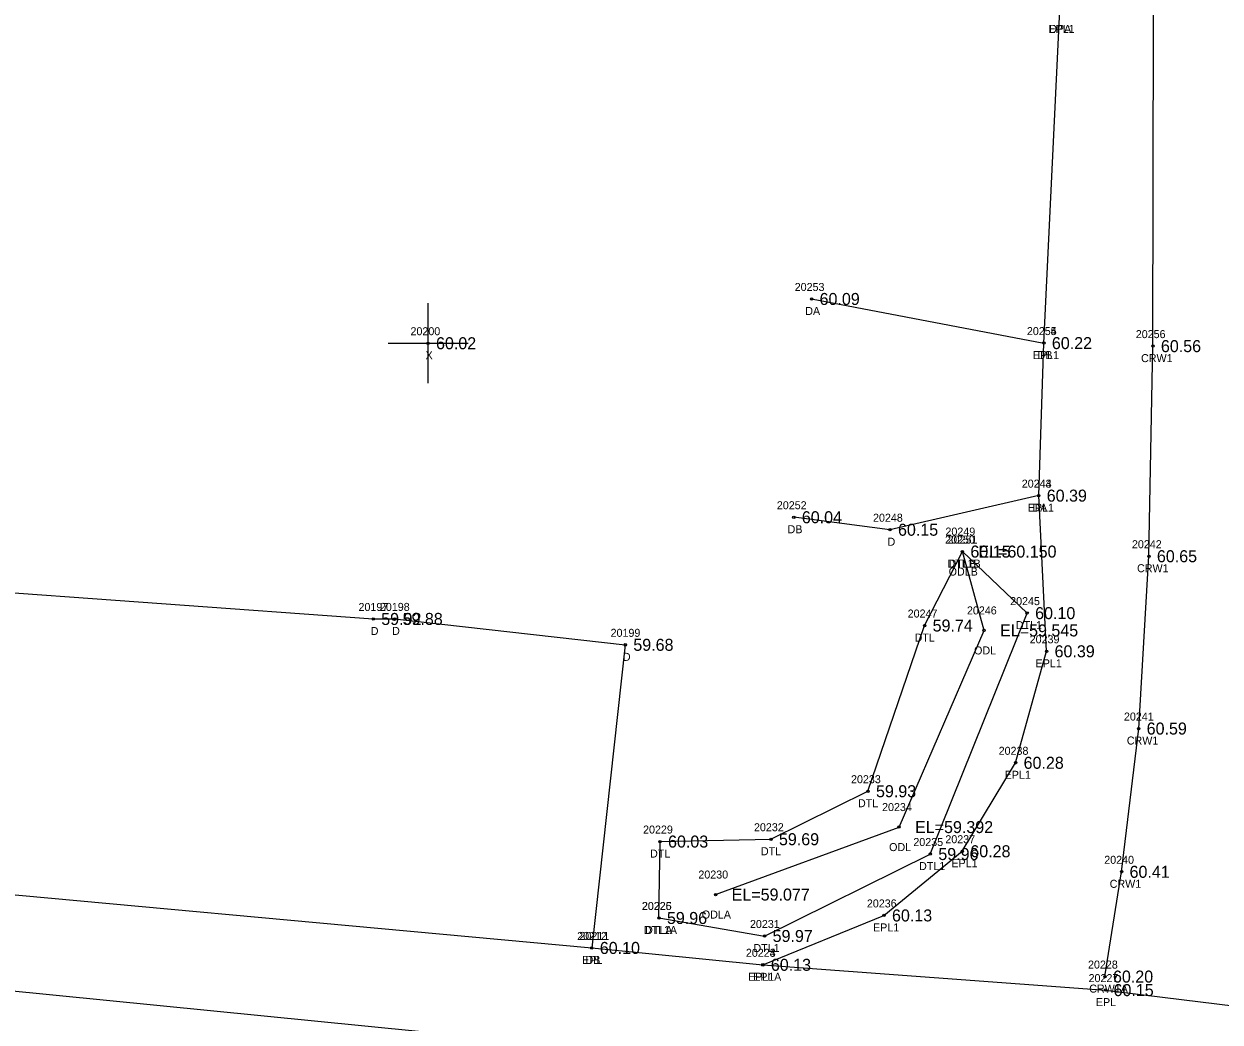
# Model space of a CAD drawing. Extents: x 2420351 to 2422725, y 845330 to 846558.
# Drawn here: x 2420818.7 to 2420968.2, y 845709.7 to 845834.4 of the extents above; entities that cross this region are included whole.
import ezdxf

# ---------------------------------------------------------------- set-up
doc = ezdxf.new("R2010")
doc.units = 0
for name, color, linetype in [('RD_DTM_BkLn1', 7, 'Continuous'), ('RD_EX_Driveway', 7, 'Continuous'), ('RD_EX_Driveway_txCode', 7, 'Continuous'), ('RD_EX_H2O', 7, 'Continuous'), ('RD_EX_H2O_txCode', 7, 'Continuous'), ('RD_EX_Misc', 7, 'Continuous'), ('RD_EX_Misc_txCode', 7, 'Continuous'), ('RD_EX_Road', 7, 'Continuous'), ('RD_EX_Road_txCode', 7, 'Continuous'), ('RD_EX_TX_Driveway_ELEV', 7, 'Continuous'), ('RD_EX_TX_H2O_ELEV', 7, 'Continuous'), ('RD_EX_TX_Misc_ELEV', 7, 'Continuous'), ('RD_EX_TX_Road_ELEV', 7, 'Continuous'), ('RD_HC_Survey_ELEV', 7, 'Continuous'), ('RD_HC_Survey_txCode', 7, 'Continuous'), ('RD_SMD_Locator', 7, 'Continuous')]:
    doc.layers.add(name, color=color, linetype=linetype)

msp = doc.modelspace()

# ---------------------------------------------------------------- linework, layer by layer
at = {"layer": 'RD_DTM_BkLn1'}
for points in [[(2420953.84, 845715.4), (2420955.91, 845728.49), (2420958.05, 845746.39), (2420959.33, 845767.92), (2420959.83, 845794.17), (2420960.04, 845896.62), (2420959.9, 845997.98), (2420960.79, 846105.06), (2420961.13, 846198.92)], [(2420378.71, 845690.53), (2420439.5, 845704.09), (2420489.95, 845712.49), (2420551.89, 845719.42), (2420551.95, 845719.57), (2420607.12, 845722.67), (2420682.92, 845723.04), (2420749.65, 845719.68), (2420796.31, 845715.7), (2420900.74, 845705.33), (2421018.16, 845694.11), (2421114.61, 845684.8), (2421175.74, 845680.1), (2421234.97, 845678.35), (2421292.42, 845679.46), (2421350.56, 845683.65), (2421414.53, 845692.12), (2421472.54, 845703.63), (2421533.08, 845718.31), (2421555.4, 845725.02), (2421609.81, 845741.71), (2421666.58, 845762.88), (2421744.67, 845798.22)]]:
    msp.add_lwpolyline(points, dxfattribs=at)
at = {"layer": 'RD_EX_Driveway'}
msp.add_line((2420917.17, 845800.06), (2420946.2, 845794.55), dxfattribs=at)
for points in [[(2420945.56, 845775.49), (2420926.97, 845771.23), (2420914.95, 845772.79)], [(2420809.42, 845763.93), (2420862.38, 845760.08), (2420865.05, 845760.09), (2420893.89, 845756.85), (2420889.7, 845718.98)]]:
    msp.add_lwpolyline(points, dxfattribs=at)
at = {"layer": 'RD_EX_H2O'}
for points in [[(2420898.09, 845722.72), (2420898.23, 845732.27), (2420912.09, 845732.56), (2420924.22, 845738.56), (2420931.3, 845759.26), (2420936.02, 845768.5)], [(2420898.09, 845722.72), (2420911.3, 845720.47), (2420932.01, 845730.71), (2420944.11, 845760.81), (2420936.02, 845768.5)], [(2420905.18, 845725.65), (2420928.1, 845734.08), (2420938.73, 845758.65), (2420936.02, 845768.5)]]:
    msp.add_lwpolyline(points, dxfattribs=at)
at = {"layer": 'RD_EX_Misc'}
for p, q in [((2420869.23, 845789.53), (2420869.23, 845799.53)), ((2420864.23, 845794.53), (2420874.23, 845794.53))]:
    msp.add_line(p, q, dxfattribs=at)
at = {"layer": 'RD_EX_Road'}
for points in [[(2420911.08, 845716.87), (2420926.22, 845723.04), (2420936.01, 845731.06), (2420942.67, 845742.11), (2420946.54, 845756.04), (2420945.56, 845775.49), (2420946.2, 845794.55), (2420948.14, 845835.31), (2420948.56, 845856.76), (2420948.65, 845897.5), (2420947.59, 845964.03), (2420948.31, 845983.28), (2420948.75, 845998.25), (2420949.7, 846105.56), (2420949.53, 846120.86), (2420949.28, 846141.3), (2420949.41, 846199.43)], [(2420376.35, 845701.93), (2420403.68, 845709.11), (2420436.45, 845715.41), (2420465.85, 845720.8), (2420487.58, 845724.76), (2420551.29, 845731.53), (2420607.05, 845734.89), (2420658.72, 845735.59), (2420682.86, 845735.47), (2420736.67, 845732.56), (2420795.4, 845727.65), (2420889.7, 845718.98), (2420911.08, 845716.87), (2420953.91, 845713.71), (2420998.34, 845708.25), (2421018.47, 845706.55), (2421116.02, 845696.98), (2421176.98, 845692), (2421235.85, 845690.14), (2421292.32, 845691.44), (2421350.22, 845695.49), (2421412.35, 845704.28)]]:
    msp.add_lwpolyline(points, dxfattribs=at)
at = {"layer": 'RD_SMD_Locator'}
for centre in [(2420917.17, 845800.06), (2420869.23, 845794.53), (2420946.2, 845794.55), (2420946.2, 845794.55), (2420959.83, 845794.17), (2420945.56, 845775.49), (2420945.56, 845775.49), (2420914.95, 845772.79), (2420926.97, 845771.23), (2420936.02, 845768.5), (2420936.02, 845768.5), (2420936.02, 845768.5), (2420959.33, 845767.92), (2420944.11, 845760.81), (2420862.38, 845760.08), (2420865.05, 845760.09), (2420931.3, 845759.26), (2420938.73, 845758.65), (2420893.89, 845756.85), (2420946.54, 845756.04), (2420958.05, 845746.39), (2420942.67, 845742.11), (2420924.22, 845738.56), (2420928.1, 845734.08), (2420898.23, 845732.27), (2420912.09, 845732.56), (2420932.01, 845730.71), (2420936.01, 845731.06), (2420955.91, 845728.49), (2420905.18, 845725.65), (2420926.22, 845723.04), (2420898.09, 845722.72), (2420898.09, 845722.72), (2420911.3, 845720.47), (2420889.7, 845718.98), (2420889.7, 845718.98), (2420911.08, 845716.87), (2420911.08, 845716.87), (2420953.84, 845715.4), (2420953.91, 845713.71)]:
    msp.add_circle(centre, 0.15, dxfattribs=at)

# ---------------------------------------------------------------- texts
at = {"layer": 'RD_EX_Driveway_txCode'}
for s, p in [('DPA', (2420946.87, 845833.31)), ('20253', (2420915.06, 845801.06)), ('DA', (2420916.38, 845798.06)), ('20254', (2420944.08, 845795.55)), ('DB', (2420945.42, 845792.55)), ('20244', (2420943.44, 845776.49)), ('20252', (2420912.83, 845773.79)), ('DA', (2420944.76, 845773.49)), ('20248', (2420924.85, 845772.23)), ('DB', (2420914.17, 845770.79)), ('D', (2420926.66, 845769.23)), ('20197', (2420860.54, 845761.08)), ('20198', (2420863.22, 845761.09)), ('D', (2420862.07, 845758.08)), ('D', (2420864.74, 845758.09)), ('20199', (2420892.05, 845757.85)), ('D', (2420893.58, 845754.85)), ('20211', (2420888.15, 845719.98)), ('DB', (2420888.92, 845716.98))]:
    msp.add_text(s, height=1, dxfattribs=at).set_placement(p)
at = {"layer": 'RD_EX_H2O_txCode'}
for s, p in [('20249', (2420933.9, 845770.5)), ('20250', (2420933.86, 845769.5)), ('20251', (2420934.18, 845769.5)), ('DTL1B', (2420934.14, 845766.5)), ('ODLB', (2420934.3, 845765.5)), ('DTLB', (2420934.3, 845766.5)), ('20245', (2420941.99, 845761.81)), ('20247', (2420929.18, 845760.26)), ('20246', (2420936.59, 845760.65)), ('DTL1', (2420942.7, 845758.81)), ('DTL', (2420930.05, 845757.26)), ('ODL', (2420937.48, 845755.65)), ('20233', (2420922.1, 845739.56)), ('DTL', (2420922.97, 845736.56)), ('20234', (2420925.98, 845736.08)), ('20229', (2420896.11, 845733.27)), ('20232', (2420909.97, 845733.56)), ('ODL', (2420926.86, 845731.08)), ('20235', (2420929.89, 845731.71)), ('DTL', (2420896.98, 845730.27)), ('DTL', (2420910.84, 845730.56)), ('DTL1', (2420930.6, 845728.71)), ('20230', (2420903.02, 845727.65)), ('20226', (2420895.95, 845723.72)), ('20225', (2420895.97, 845723.72)), ('ODLA', (2420903.45, 845722.65)), ('DTL1A', (2420896.19, 845720.72)), ('DTLA', (2420896.36, 845720.72)), ('20231', (2420909.47, 845721.47)), ('DTL1', (2420909.9, 845718.47))]:
    msp.add_text(s, height=1, dxfattribs=at).set_placement(p)
at = {"layer": 'RD_EX_Misc_txCode'}
for s, p in [('20200', (2420867.04, 845795.53)), ('X', (2420868.92, 845792.53))]:
    msp.add_text(s, height=1, dxfattribs=at).set_placement(p)
at = {"layer": 'RD_EX_Road_txCode'}
for s, p in [('EPL1', (2420946.77, 845833.31)), ('20255', (2420944.08, 845795.55)), ('EPL1', (2420944.83, 845792.55)), ('20243', (2420943.44, 845776.49)), ('EPL1', (2420944.19, 845773.49)), ('20239', (2420944.43, 845757.04)), ('EPL1', (2420945.17, 845754.04)), ('20238', (2420940.55, 845743.11)), ('EPL1', (2420941.3, 845740.11)), ('20237', (2420933.89, 845732.06)), ('EPL1', (2420934.64, 845729.06)), ('20236', (2420924.08, 845724.04)), ('EPL1', (2420924.85, 845721.04)), ('20212', (2420887.87, 845719.98)), ('20223', (2420908.96, 845717.87)), ('20224', (2420908.96, 845717.87)), ('EPL', (2420888.5, 845716.98)), ('EPL1A', (2420909.22, 845714.87)), ('EPL', (2420909.87, 845714.87)), ('20227', (2420951.79, 845714.71)), ('EPL', (2420952.7, 845711.71))]:
    msp.add_text(s, height=1, dxfattribs=at).set_placement(p)
at = {"layer": 'RD_EX_TX_Driveway_ELEV'}
for s, p in [('60.09', (2420918.17, 845799.31)), ('60.22', (2420947.2, 845793.8)), ('60.39', (2420946.56, 845774.74)), ('60.04', (2420915.95, 845772.04)), ('60.15', (2420927.97, 845770.48)), ('59.92', (2420863.38, 845759.33)), ('59.88', (2420866.05, 845759.34)), ('59.68', (2420894.89, 845756.1)), ('60.10', (2420890.7, 845718.23))]:
    msp.add_text(s, height=1.5, dxfattribs=at).set_placement(p)
at = {"layer": 'RD_EX_TX_H2O_ELEV'}
for s, p in [('60.15', (2420937.02, 845767.75)), ('60.15', (2420937.02, 845767.75)), ('EL=60.150', (2420938.02, 845767.75)), ('60.10', (2420945.11, 845760.06)), ('59.74', (2420932.3, 845758.51)), ('EL=59.545', (2420940.73, 845757.9)), ('59.93', (2420925.22, 845737.81)), ('EL=59.392', (2420930.1, 845733.33)), ('60.03', (2420899.23, 845731.52)), ('59.69', (2420913.09, 845731.81)), ('59.96', (2420933.01, 845729.96)), ('EL=59.077', (2420907.18, 845724.9)), ('59.96', (2420899.09, 845721.97)), ('59.96', (2420899.09, 845721.97)), ('59.97', (2420912.3, 845719.72))]:
    msp.add_text(s, height=1.5, dxfattribs=at).set_placement(p)
at = {"layer": 'RD_EX_TX_Misc_ELEV'}
msp.add_text('60.02', height=1.5, dxfattribs=at).set_placement((2420870.23, 845793.78))
at = {"layer": 'RD_EX_TX_Road_ELEV'}
for s, p in [('60.22', (2420947.2, 845793.8)), ('60.39', (2420946.56, 845774.74)), ('60.39', (2420947.54, 845755.29)), ('60.28', (2420943.67, 845741.36)), ('60.28', (2420937.01, 845730.31)), ('60.13', (2420927.22, 845722.29)), ('60.10', (2420890.7, 845718.23)), ('60.13', (2420912.08, 845716.12)), ('60.13', (2420912.08, 845716.12)), ('60.15', (2420954.91, 845712.96))]:
    msp.add_text(s, height=1.5, dxfattribs=at).set_placement(p)
at = {"layer": 'RD_HC_Survey_ELEV'}
for s, p in [('60.56', (2420960.83, 845793.42)), ('60.65', (2420960.33, 845767.17)), ('60.59', (2420959.05, 845745.64)), ('60.41', (2420956.91, 845727.74)), ('60.20', (2420954.84, 845714.65))]:
    msp.add_text(s, height=1.5, dxfattribs=at).set_placement(p)
at = {"layer": 'RD_HC_Survey_txCode'}
for s, p in [('20256', (2420957.69, 845795.17)), ('CRW1', (2420958.35, 845792.17)), ('20242', (2420957.21, 845768.92)), ('CRW1', (2420957.85, 845765.92)), ('20241', (2420956.21, 845747.39)), ('CRW1', (2420956.57, 845744.39)), ('20240', (2420953.75, 845729.49)), ('CRW1', (2420954.43, 845726.49)), ('20228', (2420951.72, 845716.4)), ('CRW1A', (2420951.87, 845713.4))]:
    msp.add_text(s, height=1, dxfattribs=at).set_placement(p)

doc.saveas('drawing.dxf')
